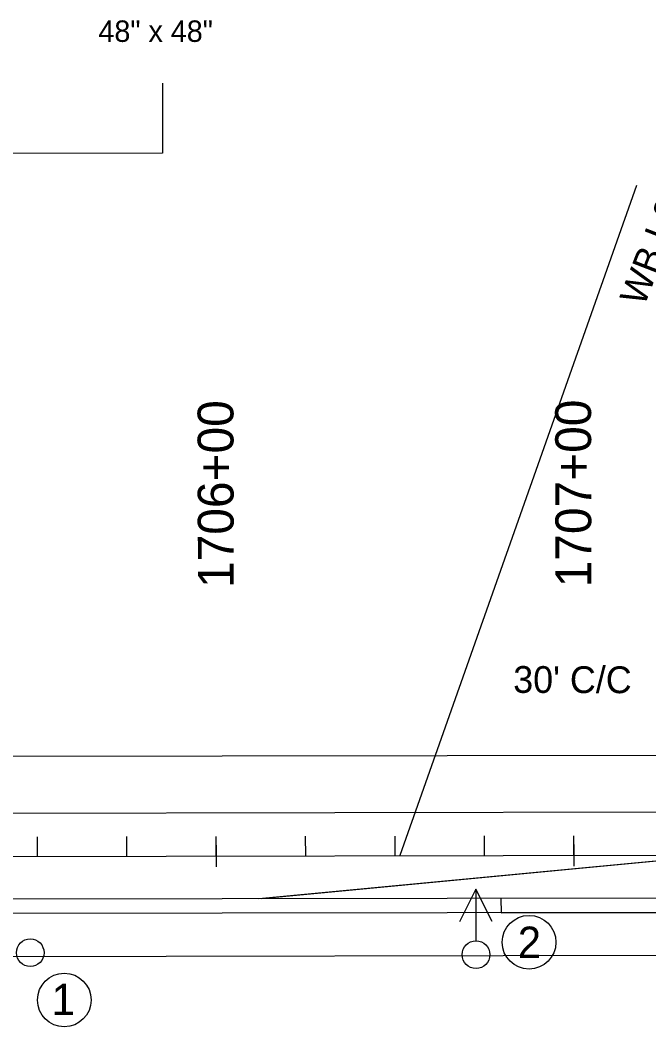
# Model space of a CAD drawing. Extents: x 16513048 to 16518780, y 7009856 to 7010869.
# Drawn here: x 16515285.9 to 16515461.8, y 7010309.1 to 7010590.8 of the extents above; entities that cross this region are included whole.
import ezdxf

# ---------------------------------------------------------------- set-up
doc = ezdxf.new("R2010")
doc.units = 0
for name, color, linetype in [('Dimensions', 7, 'Continuous'), ('dsnNonPlotable', 7, 'Continuous'), ('dsnStdLabel', 7, 'Continuous'), ('Level 2', 7, 'Continuous'), ('PavementMarking', 7, 'Continuous'), ('Shape', 7, 'Continuous'), ('SheetBorder', 7, 'Continuous'), ('tdCoTitleBlock', 7, 'Continuous')]:
    doc.layers.add(name, color=color, linetype=linetype)

msp = doc.modelspace()

# ---------------------------------------------------------------- linework, layer by layer
at = {"layer": 'dsnNonPlotable'}
for p, q in [((16515458.28, 7010544.57), (16515392.13, 7010357)), ((16513050.27, 7010352.91), (16516699.62, 7010359.27)), ((16513050.32, 7010324.91), (16515740.86, 7010329.6))]:
    msp.add_line(p, q, dxfattribs=at)
for points in [[(16513050.22, 7010380.91), (16516699.59, 7010387.27), (16518770.65, 7010388.94)], [(16518770.66, 7010372.94), (16516699.61, 7010371.27), (16513050.25, 7010364.91)], [(16515602.66, 7010360.74), (16515517.66, 7010360.59), (16515353.41, 7010344.93)], [(16518770.68, 7010348.94), (16516699.64, 7010347.27), (16513050.29, 7010340.91)], [(16518770.69, 7010344.94), (16516699.64, 7010343.27), (16513050.3, 7010336.91)]]:
    msp.add_lwpolyline(points, dxfattribs=at)
at = {"layer": 'Level 2'}
for p, q in [((16515325.74, 7010573.16), (16515325.77, 7010553.56)), ((16515325.77, 7010553.56), (16515083.27, 7010553.13)), ((16515413.38, 7010347.66), (16515408.83, 7010338.51)), ((16515413.38, 7010347.66), (16515413.41, 7010333.16)), ((16515417.97, 7010338.53), (16515413.38, 7010347.66))]:
    msp.add_line(p, q, dxfattribs=at)
for centre, radius in [((16515428.25, 7010332.76), 7.51), ((16515288.76, 7010329.83), 3.87), ((16515413.42, 7010329.28), 3.87), ((16515298.29, 7010316.6), 7.51)]:
    msp.add_circle(centre, radius, dxfattribs=at)
at = {"layer": 'PavementMarking'}
msp.add_lwpolyline([(16515602.66, 7010360.74), (16515517.66, 7010360.59), (16515352.69, 7010344.93)], dxfattribs=at)
at = {"layer": 'Shape'}
msp.add_lwpolyline([(16515561.07, 7010345.29), (16515420.4, 7010345.04), (16515420.41, 7010341.04), (16515561.08, 7010341.29), (16515561.08, 7010338.29), (16515586.59, 7010338.33), (16515631.25, 7010340.24), (16515672.07, 7010340.32), (16515672.06, 7010345.48), (16515637.06, 7010345.42), (16515637.04, 7010358.42), (16515627.04, 7010358.4), (16515627.06, 7010345.4)], close=True, dxfattribs=at)
at = {"layer": 'SheetBorder'}
for p, q in [((16515290.79, 7010356.82), (16515290.78, 7010362.28)), ((16515315.79, 7010356.86), (16515315.78, 7010362.32)), ((16515365.79, 7010356.95), (16515365.78, 7010362.41)), ((16515390.79, 7010356.99), (16515390.78, 7010362.45)), ((16515415.79, 7010357.04), (16515415.78, 7010362.5)), ((16515340.79, 7010359.97), (16515340.8, 7010353.85)), ((16515440.79, 7010360.14), (16515440.8, 7010354.02))]:
    msp.add_line(p, q, dxfattribs=at)
at = {"layer": 'tdCoTitleBlock'}
for p, q in [((16515340.79, 7010356.91), (16515340.78, 7010362.37)), ((16515440.79, 7010357.08), (16515440.78, 7010362.54))]:
    msp.add_line(p, q, dxfattribs=at)

# ---------------------------------------------------------------- texts
at = {"layer": 'Dimensions'}
for s, rotation, p in [('WB I-80 Off Ramp', 68.7814, (16515460.41, 7010510.45)), ("30' C/C", 359.8322, (16515423.81, 7010402.55))]:
    msp.add_text(s, height=7.5, rotation=rotation, dxfattribs=at).set_placement(p)
at = {"layer": 'dsnStdLabel'}
msp.add_text('48" x 48"', height=6, dxfattribs=at).set_placement((16515307.83, 7010584.71))
at = {"layer": 'Level 2'}
for s, p in [('2', (16515425.09, 7010328.38)), ('1', (16515294.74, 7010312.38))]:
    msp.add_text(s, height=8.76, dxfattribs=at).set_placement(p)
at = {"layer": 'SheetBorder'}
for s, p in [('1706+00', (16515345.67, 7010431.91)), ('1707+00', (16515445.67, 7010432.09))]:
    msp.add_text(s, height=10.02, rotation=90.0999, dxfattribs=at).set_placement(p)

doc.saveas('drawing.dxf')
